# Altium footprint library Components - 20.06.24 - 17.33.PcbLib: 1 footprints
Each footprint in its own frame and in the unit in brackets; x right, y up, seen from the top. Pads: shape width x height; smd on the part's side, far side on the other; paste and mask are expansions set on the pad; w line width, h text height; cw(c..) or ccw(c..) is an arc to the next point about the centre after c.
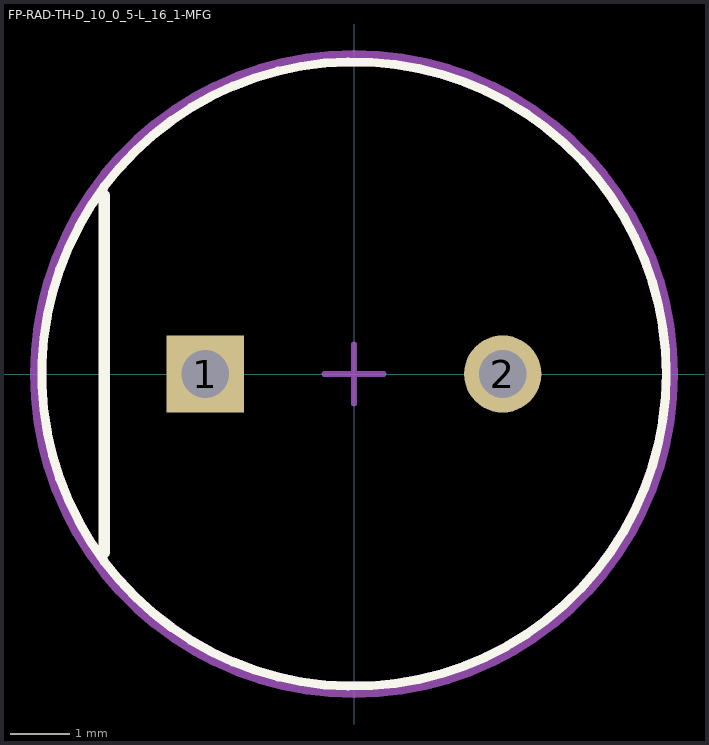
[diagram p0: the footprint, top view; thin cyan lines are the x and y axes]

## FP-RAD-TH-D_10_0_5-L_16_1-MFG [mm]
pads (2):
  rect 1.3x1.3 hole 0.8 paste-1000 mask+0: 1(-2.5,0)
  round 1.3 hole 0.8 paste-1000 mask+0: 2(2.5,0)
Top Overlay:
  circle w0.15: c0,0 r5.25
  lines w0.2: -4.2,-3 -4.2,3
Top Assembly:
  text ".Designator" at 0,0.188 h1
Top 3D Body:
  circle w0.15: c0,0 r5.25
Top Courtyard:
  lines w0.2: -5.35,0 ccw(c0,0) 5.35,0 ccw(c0,0) -5.35,0
Top Component Center:
  lines w0.1: -0.5,0 0.5,0 ; 0,-0.5 0,0.5
3D body "Cap_Panasonic_EEUTA1J470_eec.STEP": height 0.25, standoff 0, extent -5.35,-5.35 5.35,5.35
